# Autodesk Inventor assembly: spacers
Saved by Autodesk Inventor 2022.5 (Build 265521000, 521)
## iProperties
Created: 2024-12
Part Number: spacers
Document SubType Name: Assembly
Designer: AdminForWorker
Title: spacers
Author: AdminForWorker
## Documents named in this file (2)
- c:\worker\convert-fusion-r05-cosv3\tmp\job-1\35\temp\files\545dca92-a972-481a-9197-dd1a1176500e\spacers.iam
- c:\worker\convert-fusion-r05-cosv3\tmp\job-1\35\temp\files\545dca92-a972-481a-9197-dd1a1176500e\Component67.ipt
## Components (1 placed, 1 different names)
1. Component67:1
